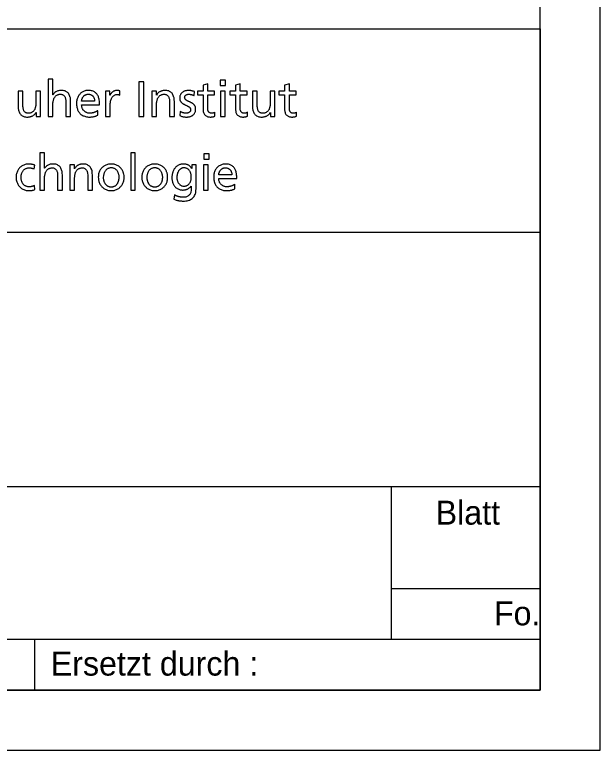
# Model space of a CAD drawing. Extents: x 0 to 238, y 0 to 168.
# Drawn here: x 228.07 to 237.8, y 0 to 12.23 of the extents above; entities that cross this region are included whole.
import ezdxf

# ---------------------------------------------------------------- set-up
doc = ezdxf.new("R2010")
doc.units = 0
doc.layers.add('90_Plankopf', color=7, linetype='Continuous')

msp = doc.modelspace()

# ---------------------------------------------------------------- linework, layer by layer
at = {"layer": '90_Plankopf'}
for p, q in [((236.8, 11.998), (236.8, 22.996)), ((201.224, 11.998), (236.8, 11.998)), ((201.224, 11.998), (236.8, 11.998)), ((236.8, 11.998), (236.8, 1)), ((236.8, 11.998), (236.8, 1)), ((229.811, 10.897), (229.811, 10.966)), ((231.046, 10.888), (231.053, 10.956)), ((229.394, 10.792), (229.177, 10.792)), ((229.177, 10.734), (229.477, 10.734)), ((229.445, 10.559), (229.445, 10.636)), ((230.814, 10.624), (230.81, 10.554)), ((231.392, 10.543), (231.392, 10.609)), ((231.933, 10.543), (231.933, 10.609)), ((232.749, 10.543), (232.749, 10.609)), ((228.39, 9.667), (228.397, 9.732)), ((231.675, 9.568), (231.457, 9.568)), ((231.457, 9.51), (231.757, 9.51)), ((228.4, 9.325), (228.394, 9.394)), ((231.725, 9.335), (231.725, 9.412)), ((230.719, 9.235), (230.711, 9.163)), ((220, 8.614), (236.8, 8.614)), ((220, 4.384), (236.8, 4.384)), ((234.329, 1.846), (234.329, 4.384)), ((234.329, 2.692), (236.8, 2.692)), ((220, 1.846), (236.8, 1.846)), ((228.4, 1), (228.4, 1.846)), ((236.8, 1), (201.224, 1)), ((203.56, 1), (236.8, 1)), ((203.56, 1), (236.8, 1))]:
    msp.add_line(p, q, dxfattribs=at)
for points in [[(0, 0), (237.8, 0), (237.8, 168.2), (0, 168.2)], [(5, 1), (236.8, 1), (236.8, 167.2), (5, 167.2)]]:
    msp.add_lwpolyline(points, close=True, dxfattribs=at)
for points in [[(228.702, 10.902), (228.7, 10.902), (228.7, 11.16), (228.623, 11.16), (228.623, 10.541), (228.7, 10.541), (228.7, 10.736)], [(231.571, 11.056), (231.571, 11.144), (231.483, 11.144), (231.483, 11.056), (231.571, 11.056)], [(230.129, 10.541), (230.212, 10.541), (230.212, 11.117), (230.129, 11.117), (230.129, 10.541)], [(231.274, 10.669), (231.274, 10.899), (231.386, 10.899), (231.386, 10.962), (231.274, 10.962), (231.274, 11.084), (231.197, 11.059), (231.197, 10.962), (231.102, 10.962), (231.102, 10.899), (231.197, 10.899), (231.197, 10.653)], [(231.815, 10.669), (231.815, 10.899), (231.927, 10.899), (231.927, 10.962), (231.815, 10.962), (231.815, 11.084), (231.738, 11.059), (231.738, 10.962), (231.643, 10.962), (231.643, 10.899), (231.738, 10.899), (231.738, 10.653)], [(232.631, 10.669), (232.631, 10.899), (232.742, 10.899), (232.742, 10.962), (232.631, 10.962), (232.631, 11.084), (232.553, 11.059), (232.553, 10.962), (232.458, 10.962), (232.458, 10.899), (232.553, 10.899), (232.553, 10.653)], [(228.201, 10.744), (228.201, 10.962), (228.123, 10.962), (228.123, 10.712)], [(228.419, 10.608), (228.42, 10.608), (228.42, 10.541), (228.495, 10.541), (228.495, 10.962), (228.418, 10.962), (228.418, 10.767)], [(229.65, 10.897), (229.649, 10.897), (229.649, 10.962), (229.576, 10.962), (229.576, 10.541), (229.654, 10.541), (229.654, 10.733)], [(230.423, 10.895), (230.422, 10.895), (230.422, 10.962), (230.346, 10.962), (230.346, 10.541), (230.424, 10.541), (230.424, 10.736)], [(231.488, 10.962), (231.488, 10.541), (231.566, 10.541), (231.566, 10.962), (231.488, 10.962)], [(232.097, 10.744), (232.097, 10.962), (232.019, 10.962), (232.019, 10.712)], [(232.315, 10.608), (232.316, 10.608), (232.316, 10.541), (232.391, 10.541), (232.391, 10.962), (232.314, 10.962), (232.314, 10.767)], [(228.917, 10.759), (228.917, 10.541), (228.995, 10.541), (228.995, 10.791)], [(230.641, 10.759), (230.641, 10.541), (230.719, 10.541), (230.719, 10.791)], [(228.564, 9.678), (228.562, 9.678), (228.562, 9.936), (228.484, 9.936), (228.484, 9.317), (228.562, 9.317), (228.562, 9.512)], [(229.993, 9.317), (230.07, 9.317), (230.07, 9.936), (229.993, 9.936), (229.993, 9.317)], [(231.299, 9.832), (231.299, 9.92), (231.211, 9.92), (231.211, 9.832), (231.299, 9.832)], [(229.061, 9.671), (229.059, 9.671), (229.059, 9.738), (228.984, 9.738), (228.984, 9.317), (229.061, 9.317), (229.061, 9.512)], [(231.079, 9.335), (231.079, 9.738), (231.007, 9.738), (231.007, 9.676), (231.006, 9.676)], [(231.206, 9.738), (231.206, 9.317), (231.284, 9.317), (231.284, 9.738), (231.206, 9.738)], [(228.779, 9.535), (228.779, 9.317), (228.857, 9.317), (228.857, 9.567)], [(229.279, 9.535), (229.279, 9.317), (229.356, 9.317), (229.356, 9.567)], [(231, 9.382), (231.001, 9.382), (231.001, 9.341)]]:
    msp.add_lwpolyline(points, dxfattribs=at)
for points in [[(228.7, 10.736), (228.7, 10.762), (228.703, 10.785), (228.708, 10.806), (228.713, 10.827), (228.721, 10.846), (228.731, 10.861), (228.742, 10.876), (228.755, 10.888), (228.771, 10.897), (228.787, 10.905), (228.806, 10.909), (228.828, 10.909), (228.851, 10.908), (228.868, 10.902), (228.881, 10.89), (228.895, 10.879), (228.904, 10.862), (228.909, 10.841), (228.915, 10.819), (228.917, 10.792), (228.917, 10.759)], [(228.995, 10.791), (228.995, 10.829), (228.989, 10.861), (228.978, 10.888), (228.967, 10.915), (228.95, 10.936), (228.927, 10.95), (228.903, 10.965), (228.874, 10.972), (228.837, 10.972), (228.808, 10.972), (228.781, 10.966), (228.758, 10.954), (228.735, 10.942), (228.716, 10.924), (228.702, 10.902)], [(229.477, 10.734), (229.477, 10.768), (229.474, 10.8), (229.468, 10.829), (229.461, 10.857), (229.451, 10.882), (229.437, 10.904), (229.422, 10.925), (229.403, 10.942), (229.38, 10.954), (229.356, 10.966), (229.326, 10.972), (229.291, 10.972), (229.261, 10.972), (229.235, 10.967), (229.21, 10.956), (229.186, 10.946), (229.165, 10.931), (229.148, 10.912), (229.131, 10.893), (229.117, 10.871), (229.108, 10.845), (229.099, 10.819), (229.094, 10.79), (229.094, 10.759), (229.094, 10.725), (229.098, 10.694), (229.107, 10.666), (229.116, 10.638), (229.129, 10.614), (229.147, 10.594), (229.165, 10.574), (229.187, 10.558), (229.215, 10.548), (229.242, 10.537), (229.275, 10.531), (229.312, 10.531), (229.335, 10.531), (229.354, 10.533), (229.371, 10.536), (229.387, 10.539), (229.401, 10.543), (229.413, 10.547), (229.424, 10.551), (229.435, 10.555), (229.445, 10.559)], [(229.177, 10.792), (229.178, 10.806), (229.181, 10.82), (229.186, 10.833), (229.191, 10.847), (229.198, 10.86), (229.207, 10.871), (229.216, 10.883), (229.227, 10.892), (229.241, 10.899), (229.254, 10.906), (229.271, 10.909), (229.29, 10.909), (229.306, 10.909), (229.321, 10.906), (229.334, 10.9), (229.347, 10.894), (229.358, 10.886), (229.367, 10.875), (229.376, 10.864), (229.383, 10.852), (229.387, 10.838), (229.392, 10.823), (229.394, 10.808), (229.394, 10.792)], [(229.811, 10.966), (229.806, 10.967), (229.801, 10.968), (229.796, 10.969), (229.791, 10.97), (229.786, 10.971), (229.78, 10.971), (229.774, 10.972), (229.768, 10.972), (229.76, 10.972), (229.745, 10.972), (229.731, 10.969), (229.716, 10.962), (229.702, 10.956), (229.69, 10.947), (229.678, 10.936), (229.667, 10.925), (229.657, 10.912), (229.65, 10.897)], [(229.654, 10.733), (229.654, 10.768), (229.659, 10.799), (229.668, 10.824), (229.678, 10.85), (229.691, 10.87), (229.708, 10.883), (229.725, 10.897), (229.745, 10.904), (229.768, 10.904), (229.775, 10.904), (229.782, 10.904), (229.79, 10.903), (229.797, 10.902), (229.804, 10.9), (229.811, 10.897)], [(230.719, 10.791), (230.719, 10.829), (230.713, 10.861), (230.702, 10.888), (230.691, 10.915), (230.674, 10.936), (230.65, 10.95), (230.627, 10.965), (230.597, 10.972), (230.561, 10.972), (230.541, 10.972), (230.522, 10.969), (230.504, 10.963), (230.486, 10.957), (230.47, 10.948), (230.456, 10.936), (230.442, 10.925), (230.431, 10.911), (230.423, 10.895)], [(230.424, 10.736), (230.424, 10.762), (230.426, 10.785), (230.432, 10.806), (230.437, 10.827), (230.444, 10.846), (230.455, 10.861), (230.465, 10.876), (230.479, 10.888), (230.495, 10.897), (230.511, 10.905), (230.53, 10.909), (230.552, 10.909), (230.574, 10.908), (230.592, 10.902), (230.605, 10.89), (230.618, 10.879), (230.627, 10.862), (230.633, 10.841), (230.639, 10.819), (230.641, 10.792), (230.641, 10.759)], [(231.053, 10.956), (231.038, 10.96), (231.022, 10.964), (231.007, 10.967), (230.991, 10.97), (230.974, 10.972), (230.956, 10.972), (230.936, 10.972), (230.916, 10.969), (230.898, 10.964), (230.88, 10.959), (230.864, 10.951), (230.851, 10.94), (230.837, 10.929), (230.827, 10.916), (230.819, 10.9), (230.812, 10.883), (230.808, 10.864), (230.808, 10.842), (230.808, 10.826), (230.811, 10.811), (230.818, 10.799), (230.825, 10.787), (230.833, 10.776), (230.844, 10.767), (230.855, 10.758), (230.867, 10.75), (230.88, 10.743), (230.893, 10.736), (230.906, 10.729), (230.919, 10.723), (230.931, 10.717), (230.943, 10.711), (230.954, 10.704), (230.965, 10.698), (230.974, 10.691), (230.98, 10.683), (230.987, 10.675), (230.99, 10.665), (230.99, 10.654), (230.99, 10.643), (230.988, 10.633), (230.983, 10.626), (230.978, 10.618), (230.972, 10.612), (230.964, 10.607), (230.956, 10.602), (230.948, 10.599), (230.938, 10.597), (230.929, 10.595), (230.92, 10.594), (230.911, 10.594), (230.903, 10.594), (230.894, 10.595), (230.883, 10.597), (230.872, 10.599), (230.86, 10.603), (230.848, 10.607), (230.836, 10.612), (230.825, 10.617), (230.814, 10.624)], [(230.81, 10.554), (230.828, 10.545), (230.847, 10.539), (230.867, 10.536), (230.886, 10.532), (230.906, 10.531), (230.926, 10.531), (230.945, 10.531), (230.963, 10.534), (230.98, 10.539), (230.998, 10.544), (231.014, 10.552), (231.028, 10.563), (231.041, 10.574), (231.052, 10.588), (231.06, 10.604), (231.069, 10.621), (231.073, 10.64), (231.073, 10.662), (231.073, 10.682), (231.069, 10.698), (231.063, 10.711), (231.056, 10.724), (231.047, 10.736), (231.037, 10.745), (231.026, 10.754), (231.014, 10.762), (231.001, 10.769), (230.988, 10.776), (230.975, 10.782), (230.962, 10.787), (230.949, 10.793), (230.937, 10.799), (230.927, 10.805), (230.916, 10.812), (230.907, 10.819), (230.9, 10.827), (230.894, 10.836), (230.891, 10.846), (230.89, 10.858), (230.891, 10.87), (230.894, 10.879), (230.901, 10.887), (230.908, 10.894), (230.917, 10.9), (230.928, 10.904), (230.939, 10.908), (230.951, 10.909), (230.965, 10.909), (230.969, 10.909), (230.975, 10.909), (230.983, 10.908), (230.99, 10.906), (230.998, 10.905), (231.006, 10.903), (231.014, 10.901), (231.022, 10.898), (231.029, 10.896), (231.036, 10.893), (231.042, 10.891), (231.046, 10.888)], [(228.418, 10.767), (228.418, 10.742), (228.415, 10.718), (228.41, 10.697), (228.405, 10.676), (228.398, 10.658), (228.387, 10.642), (228.377, 10.627), (228.363, 10.615), (228.347, 10.607), (228.331, 10.598), (228.312, 10.594), (228.29, 10.594), (228.268, 10.595), (228.25, 10.602), (228.237, 10.613), (228.224, 10.624), (228.214, 10.641), (228.209, 10.662), (228.203, 10.684), (228.201, 10.711), (228.201, 10.744)], [(232.314, 10.767), (232.314, 10.742), (232.311, 10.718), (232.306, 10.697), (232.301, 10.676), (232.293, 10.658), (232.283, 10.642), (232.272, 10.627), (232.259, 10.615), (232.243, 10.607), (232.227, 10.598), (232.208, 10.594), (232.186, 10.594), (232.163, 10.595), (232.146, 10.602), (232.133, 10.613), (232.119, 10.624), (232.11, 10.641), (232.105, 10.662), (232.099, 10.684), (232.097, 10.711), (232.097, 10.744)], [(228.123, 10.712), (228.123, 10.674), (228.129, 10.642), (228.14, 10.615), (228.151, 10.588), (228.168, 10.567), (228.192, 10.553), (228.215, 10.539), (228.245, 10.531), (228.281, 10.531), (228.301, 10.531), (228.32, 10.534), (228.338, 10.54), (228.356, 10.547), (228.372, 10.555), (228.386, 10.567), (228.4, 10.578), (228.411, 10.592), (228.419, 10.608)], [(229.445, 10.636), (229.44, 10.632), (229.433, 10.628), (229.424, 10.623), (229.415, 10.618), (229.404, 10.614), (229.392, 10.609), (229.38, 10.605), (229.368, 10.601), (229.354, 10.598), (229.341, 10.596), (229.328, 10.594), (229.315, 10.594), (229.297, 10.594), (229.279, 10.597), (229.263, 10.604), (229.246, 10.611), (229.231, 10.621), (229.218, 10.633), (229.205, 10.645), (229.195, 10.66), (229.188, 10.677), (229.181, 10.694), (229.177, 10.713), (229.177, 10.734)], [(231.197, 10.653), (231.197, 10.625), (231.202, 10.602), (231.213, 10.584), (231.223, 10.566), (231.238, 10.553), (231.257, 10.544), (231.277, 10.536), (231.299, 10.531), (231.326, 10.531), (231.339, 10.531), (231.351, 10.533), (231.362, 10.535), (231.373, 10.538), (231.384, 10.54), (231.392, 10.543)], [(231.392, 10.609), (231.387, 10.605), (231.379, 10.602), (231.371, 10.599), (231.362, 10.596), (231.351, 10.594), (231.34, 10.594), (231.328, 10.594), (231.317, 10.597), (231.307, 10.603), (231.297, 10.608), (231.289, 10.617), (231.283, 10.628), (231.277, 10.639), (231.274, 10.653), (231.274, 10.669)], [(231.738, 10.653), (231.738, 10.625), (231.743, 10.602), (231.753, 10.584), (231.764, 10.566), (231.779, 10.553), (231.798, 10.544), (231.817, 10.536), (231.84, 10.531), (231.867, 10.531), (231.88, 10.531), (231.892, 10.533), (231.903, 10.535), (231.914, 10.538), (231.924, 10.54), (231.933, 10.543)], [(231.933, 10.609), (231.927, 10.605), (231.92, 10.602), (231.911, 10.599), (231.903, 10.596), (231.892, 10.594), (231.88, 10.594), (231.868, 10.594), (231.857, 10.597), (231.848, 10.603), (231.838, 10.608), (231.83, 10.617), (231.824, 10.628), (231.818, 10.639), (231.815, 10.653), (231.815, 10.669)], [(232.019, 10.712), (232.019, 10.674), (232.025, 10.642), (232.036, 10.615), (232.047, 10.588), (232.064, 10.567), (232.087, 10.553), (232.111, 10.539), (232.14, 10.531), (232.177, 10.531), (232.196, 10.531), (232.215, 10.534), (232.233, 10.54), (232.251, 10.547), (232.267, 10.555), (232.282, 10.567), (232.296, 10.578), (232.307, 10.592), (232.315, 10.608)], [(232.553, 10.653), (232.553, 10.625), (232.559, 10.602), (232.569, 10.584), (232.579, 10.566), (232.594, 10.553), (232.614, 10.544), (232.633, 10.536), (232.656, 10.531), (232.683, 10.531), (232.695, 10.531), (232.707, 10.533), (232.718, 10.535), (232.73, 10.538), (232.74, 10.54), (232.749, 10.543)], [(232.749, 10.609), (232.743, 10.605), (232.736, 10.602), (232.727, 10.599), (232.718, 10.596), (232.708, 10.594), (232.696, 10.594), (232.684, 10.594), (232.673, 10.597), (232.663, 10.603), (232.653, 10.608), (232.646, 10.617), (232.64, 10.628), (232.634, 10.639), (232.631, 10.653), (232.631, 10.669)], [(228.397, 9.732), (228.389, 9.735), (228.38, 9.737), (228.37, 9.74), (228.359, 9.742), (228.348, 9.744), (228.336, 9.746), (228.324, 9.747), (228.313, 9.748), (228.303, 9.748), (228.27, 9.748), (228.241, 9.742), (228.215, 9.732), (228.189, 9.721), (228.166, 9.706), (228.147, 9.686), (228.128, 9.666), (228.114, 9.643), (228.104, 9.616), (228.093, 9.589), (228.088, 9.56), (228.088, 9.528), (228.088, 9.498), (228.094, 9.469), (228.104, 9.442), (228.114, 9.416), (228.129, 9.393), (228.148, 9.372), (228.167, 9.352), (228.189, 9.336), (228.216, 9.325), (228.242, 9.313), (228.271, 9.308), (228.303, 9.307), (228.312, 9.307), (228.322, 9.308), (228.333, 9.309), (228.344, 9.309), (228.355, 9.311), (228.367, 9.314), (228.378, 9.316), (228.389, 9.32), (228.4, 9.325)], [(228.394, 9.394), (228.386, 9.389), (228.377, 9.384), (228.368, 9.381), (228.359, 9.377), (228.349, 9.375), (228.339, 9.373), (228.329, 9.371), (228.32, 9.37), (228.311, 9.37), (228.291, 9.37), (228.273, 9.373), (228.258, 9.379), (228.243, 9.385), (228.23, 9.393), (228.218, 9.404), (228.207, 9.414), (228.198, 9.426), (228.191, 9.44), (228.184, 9.453), (228.179, 9.467), (228.176, 9.482), (228.172, 9.498), (228.171, 9.513), (228.171, 9.528), (228.171, 9.548), (228.174, 9.568), (228.18, 9.586), (228.186, 9.605), (228.194, 9.622), (228.206, 9.637), (228.217, 9.652), (228.231, 9.663), (228.248, 9.672), (228.265, 9.681), (228.284, 9.685), (228.306, 9.685), (228.319, 9.685), (228.332, 9.684), (228.346, 9.681), (228.361, 9.678), (228.375, 9.673), (228.39, 9.667)], [(228.562, 9.512), (228.562, 9.538), (228.565, 9.561), (228.57, 9.582), (228.575, 9.604), (228.582, 9.622), (228.593, 9.637), (228.603, 9.653), (228.617, 9.664), (228.633, 9.673), (228.649, 9.681), (228.668, 9.685), (228.69, 9.685), (228.712, 9.684), (228.73, 9.678), (228.743, 9.666), (228.756, 9.655), (228.765, 9.639), (228.771, 9.617), (228.777, 9.595), (228.779, 9.568), (228.779, 9.535)], [(228.857, 9.567), (228.857, 9.605), (228.851, 9.638), (228.84, 9.665), (228.829, 9.691), (228.812, 9.712), (228.788, 9.726), (228.765, 9.741), (228.735, 9.748), (228.699, 9.748), (228.669, 9.748), (228.643, 9.742), (228.62, 9.73), (228.597, 9.718), (228.578, 9.7), (228.564, 9.678)], [(229.356, 9.567), (229.356, 9.605), (229.351, 9.638), (229.339, 9.665), (229.328, 9.691), (229.311, 9.712), (229.288, 9.726), (229.265, 9.741), (229.235, 9.748), (229.198, 9.748), (229.179, 9.748), (229.16, 9.745), (229.142, 9.739), (229.124, 9.733), (229.108, 9.724), (229.094, 9.712), (229.08, 9.701), (229.068, 9.687), (229.061, 9.671)], [(229.061, 9.512), (229.061, 9.538), (229.064, 9.561), (229.069, 9.582), (229.074, 9.604), (229.082, 9.622), (229.092, 9.637), (229.103, 9.653), (229.116, 9.664), (229.132, 9.673), (229.148, 9.681), (229.167, 9.685), (229.189, 9.685), (229.212, 9.684), (229.23, 9.678), (229.243, 9.666), (229.256, 9.655), (229.265, 9.639), (229.27, 9.617), (229.276, 9.595), (229.279, 9.568), (229.279, 9.535)], [(229.879, 9.578), (229.876, 9.591), (229.873, 9.604), (229.868, 9.616), (229.858, 9.643), (229.844, 9.666), (229.825, 9.686), (229.806, 9.706), (229.783, 9.721), (229.757, 9.732), (229.731, 9.742), (229.702, 9.748), (229.67, 9.748), (229.638, 9.748), (229.608, 9.742), (229.582, 9.732), (229.556, 9.721), (229.533, 9.706), (229.514, 9.686), (229.495, 9.666), (229.481, 9.643), (229.471, 9.616), (229.46, 9.589), (229.455, 9.56), (229.455, 9.528)], [(229.538, 9.528), (229.538, 9.548), (229.541, 9.568), (229.547, 9.586), (229.553, 9.605), (229.561, 9.622), (229.573, 9.637), (229.584, 9.652), (229.598, 9.663), (229.614, 9.672), (229.63, 9.681), (229.649, 9.685), (229.67, 9.685), (229.69, 9.685), (229.709, 9.681), (229.725, 9.672), (229.741, 9.663), (229.755, 9.652), (229.766, 9.637), (229.778, 9.622), (229.786, 9.605), (229.792, 9.586), (229.798, 9.568), (229.801, 9.548), (229.801, 9.528), (229.801, 9.513), (229.799, 9.498), (229.796, 9.482), (229.793, 9.467), (229.788, 9.453), (229.781, 9.44), (229.774, 9.426), (229.766, 9.414), (229.755, 9.404), (229.745, 9.393), (229.733, 9.385), (229.718, 9.379), (229.704, 9.373), (229.688, 9.37), (229.67, 9.37), (229.652, 9.37), (229.635, 9.373), (229.621, 9.379), (229.607, 9.385), (229.594, 9.393), (229.584, 9.404), (229.573, 9.414), (229.565, 9.426), (229.558, 9.44), (229.551, 9.453), (229.546, 9.467), (229.543, 9.482), (229.539, 9.498), (229.538, 9.513), (229.538, 9.528)], [(230.603, 9.578), (230.6, 9.591), (230.597, 9.604), (230.592, 9.616), (230.582, 9.643), (230.568, 9.666), (230.549, 9.686), (230.53, 9.706), (230.507, 9.721), (230.481, 9.732), (230.455, 9.742), (230.426, 9.748), (230.394, 9.748), (230.362, 9.748), (230.332, 9.742), (230.306, 9.732), (230.28, 9.721), (230.257, 9.706), (230.238, 9.686), (230.219, 9.666), (230.205, 9.643), (230.195, 9.616), (230.185, 9.589), (230.179, 9.56), (230.179, 9.528)], [(230.262, 9.528), (230.262, 9.548), (230.265, 9.568), (230.271, 9.586), (230.277, 9.605), (230.285, 9.622), (230.297, 9.637), (230.308, 9.652), (230.322, 9.663), (230.338, 9.672), (230.354, 9.681), (230.373, 9.685), (230.394, 9.685), (230.415, 9.685), (230.433, 9.681), (230.449, 9.672), (230.465, 9.663), (230.479, 9.652), (230.49, 9.637), (230.502, 9.622), (230.51, 9.605), (230.516, 9.586), (230.522, 9.568), (230.525, 9.548), (230.525, 9.528), (230.525, 9.513), (230.523, 9.498), (230.52, 9.482), (230.517, 9.467), (230.512, 9.453), (230.505, 9.44), (230.498, 9.426), (230.49, 9.414), (230.479, 9.404), (230.469, 9.393), (230.457, 9.385), (230.442, 9.379), (230.428, 9.373), (230.412, 9.37), (230.394, 9.37), (230.376, 9.37), (230.359, 9.373), (230.345, 9.379), (230.331, 9.385), (230.318, 9.393), (230.308, 9.404), (230.297, 9.414), (230.289, 9.426), (230.282, 9.44), (230.275, 9.453), (230.27, 9.467), (230.267, 9.482), (230.263, 9.498), (230.262, 9.513), (230.262, 9.528)], [(231.006, 9.676), (230.998, 9.691), (230.988, 9.704), (230.976, 9.715), (230.964, 9.725), (230.949, 9.734), (230.931, 9.739), (230.913, 9.745), (230.891, 9.748), (230.867, 9.748), (230.841, 9.748), (230.819, 9.744), (230.799, 9.735), (230.778, 9.727), (230.761, 9.715), (230.746, 9.7), (230.731, 9.686), (230.718, 9.669), (230.708, 9.65), (230.698, 9.631), (230.691, 9.611), (230.686, 9.589), (230.681, 9.568), (230.679, 9.546), (230.679, 9.524), (230.679, 9.497), (230.682, 9.471), (230.69, 9.446), (230.697, 9.421), (230.709, 9.399), (230.724, 9.38), (230.738, 9.361), (230.757, 9.345), (230.78, 9.334), (230.802, 9.323), (230.829, 9.318), (230.859, 9.317), (230.877, 9.317), (230.894, 9.32), (230.912, 9.324), (230.929, 9.329), (230.945, 9.337), (230.96, 9.346), (230.976, 9.356), (230.989, 9.368), (231, 9.382)], [(230.878, 9.38), (230.86, 9.38), (230.844, 9.384), (230.83, 9.392), (230.815, 9.4), (230.803, 9.411), (230.793, 9.425), (230.782, 9.438), (230.775, 9.454), (230.769, 9.472), (230.764, 9.49), (230.761, 9.509), (230.761, 9.529), (230.761, 9.543), (230.763, 9.558), (230.766, 9.572), (230.769, 9.587), (230.774, 9.601), (230.78, 9.615), (230.786, 9.628), (230.794, 9.64), (230.803, 9.651), (230.813, 9.661), (230.824, 9.67), (230.836, 9.676), (230.849, 9.682), (230.863, 9.685), (230.878, 9.685), (230.899, 9.685), (230.917, 9.681), (230.933, 9.672), (230.948, 9.664), (230.961, 9.652), (230.971, 9.637), (230.981, 9.622), (230.989, 9.605), (230.994, 9.585), (230.999, 9.566), (231.001, 9.545), (231.001, 9.523), (231.001, 9.503), (230.998, 9.485), (230.993, 9.467), (230.987, 9.45), (230.978, 9.435), (230.967, 9.422), (230.956, 9.409), (230.943, 9.399), (230.928, 9.391), (230.913, 9.384), (230.897, 9.38), (230.878, 9.38)], [(231.757, 9.51), (231.757, 9.544), (231.754, 9.576), (231.748, 9.605), (231.742, 9.634), (231.731, 9.659), (231.717, 9.68), (231.702, 9.701), (231.683, 9.718), (231.66, 9.73), (231.636, 9.742), (231.606, 9.748), (231.571, 9.748), (231.542, 9.748), (231.515, 9.743), (231.49, 9.732), (231.466, 9.722), (231.445, 9.707), (231.428, 9.688), (231.411, 9.669), (231.397, 9.647), (231.388, 9.621), (231.379, 9.595), (231.374, 9.567), (231.374, 9.535), (231.374, 9.501), (231.378, 9.47), (231.387, 9.442), (231.396, 9.414), (231.409, 9.39), (231.427, 9.37), (231.445, 9.35), (231.468, 9.334), (231.495, 9.324), (231.522, 9.313), (231.555, 9.308), (231.592, 9.307), (231.615, 9.308), (231.634, 9.309), (231.651, 9.312), (231.667, 9.315), (231.681, 9.319), (231.693, 9.323), (231.704, 9.327), (231.715, 9.331), (231.725, 9.335)], [(231.457, 9.568), (231.458, 9.582), (231.461, 9.596), (231.466, 9.609), (231.471, 9.623), (231.478, 9.636), (231.487, 9.647), (231.496, 9.659), (231.507, 9.668), (231.521, 9.675), (231.534, 9.682), (231.551, 9.685), (231.57, 9.685), (231.586, 9.685), (231.601, 9.682), (231.614, 9.676), (231.627, 9.67), (231.638, 9.662), (231.647, 9.651), (231.656, 9.64), (231.663, 9.628), (231.668, 9.614), (231.672, 9.6), (231.675, 9.584), (231.675, 9.568)], [(229.455, 9.528), (229.455, 9.498), (229.461, 9.469), (229.471, 9.442), (229.481, 9.416), (229.496, 9.393), (229.515, 9.372), (229.534, 9.352), (229.556, 9.336), (229.583, 9.325), (229.609, 9.313), (229.638, 9.308), (229.67, 9.307), (229.701, 9.308), (229.731, 9.313), (229.756, 9.325), (229.783, 9.336), (229.805, 9.352), (229.824, 9.372), (229.843, 9.393), (229.858, 9.416), (229.868, 9.442), (229.878, 9.469), (229.883, 9.498), (229.884, 9.528), (229.884, 9.545), (229.882, 9.562), (229.879, 9.578)], [(230.179, 9.528), (230.179, 9.498), (230.185, 9.469), (230.195, 9.442), (230.205, 9.416), (230.22, 9.393), (230.239, 9.372), (230.258, 9.352), (230.281, 9.336), (230.307, 9.325), (230.333, 9.313), (230.362, 9.308), (230.394, 9.307), (230.426, 9.308), (230.455, 9.313), (230.481, 9.325), (230.507, 9.336), (230.529, 9.352), (230.548, 9.372), (230.567, 9.393), (230.582, 9.416), (230.592, 9.442), (230.602, 9.469), (230.607, 9.498), (230.608, 9.528), (230.608, 9.545), (230.606, 9.562), (230.603, 9.578)], [(231.725, 9.412), (231.72, 9.408), (231.713, 9.404), (231.704, 9.399), (231.695, 9.394), (231.684, 9.39), (231.672, 9.385), (231.66, 9.381), (231.648, 9.377), (231.634, 9.374), (231.621, 9.372), (231.608, 9.37), (231.595, 9.37), (231.577, 9.37), (231.559, 9.374), (231.543, 9.38), (231.526, 9.387), (231.511, 9.397), (231.498, 9.409), (231.486, 9.421), (231.475, 9.436), (231.468, 9.453), (231.461, 9.471), (231.457, 9.49), (231.457, 9.51)], [(230.711, 9.163), (230.733, 9.155), (230.753, 9.149), (230.77, 9.145), (230.787, 9.141), (230.803, 9.138), (230.818, 9.136), (230.833, 9.135), (230.847, 9.134), (230.862, 9.134), (230.912, 9.134), (230.953, 9.142), (230.985, 9.158), (231.017, 9.174), (231.041, 9.196), (231.056, 9.226), (231.072, 9.256), (231.079, 9.293), (231.079, 9.335)], [(231.001, 9.341), (231.001, 9.311), (230.996, 9.286), (230.986, 9.264), (230.975, 9.243), (230.961, 9.226), (230.941, 9.214), (230.922, 9.203), (230.898, 9.197), (230.871, 9.197), (230.857, 9.197), (230.844, 9.197), (230.832, 9.199), (230.819, 9.2), (230.808, 9.203), (230.796, 9.206), (230.784, 9.209), (230.772, 9.212), (230.76, 9.217), (230.747, 9.222), (230.734, 9.228), (230.719, 9.235)]]:
    msp.add_open_spline(points, degree=3, dxfattribs=at)

# ---------------------------------------------------------------- texts
for s, p in [('Blatt', (235.063, 3.752)), ('Fo.', (236.032, 2.078)), ('Ersetzt durch :', (228.665, 1.242))]:
    msp.add_text(s, height=0.4, dxfattribs=at).set_placement(p)

doc.saveas('drawing.dxf')
